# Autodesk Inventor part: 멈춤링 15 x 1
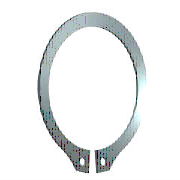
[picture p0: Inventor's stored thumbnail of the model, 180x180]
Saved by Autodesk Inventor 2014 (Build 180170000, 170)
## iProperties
Created: 2012-02
Part Number: 멈춤링 15 x 1
Material: 강철, 연강
Description: 리테이닝 링(C형)
Document SubType Name: Modeling
Standard: KS B 1336
Designer: mduedu
Standards Organization: KS
Language: ko-KR
Size Designation: 15 x 1
Categories: <MemberInstance><Categories><Category DisplayName="샤프트 부품" InternalName="7f7aeb1f-a693-4053-b835-cee3144e0d98" Mnemonic="SHFT"><Category DisplayName="써클립" Inter
Density: 1 g/cm^3
Appearance: 파란색 - 벽 페인트 - 광택
IsCustomPart: 1
Author: mduedu
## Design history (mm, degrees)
sketch "스케치1"
  geometry: L1 (-6, 0)-(6, 0) reference; L2 (0, 20.189)-(0, -80.536) reference; L3 (-48.09, 0)-(48.09, 0) reference; L4 (-0.425, -14.637)-(-0.425, -18.137); L5 (-0.425, -6.54)-(-0.425, -13.29); L6 (-2.795, 2.1)-(3.672, 2.1); L7 (0.425, -6.54)-(0.425, -13.29); L8 (0.425, -14.637)-(0.425, -18.137); C1 r 0.85 at (-1.7, -16.283); C2 r 0.85 at (1.7, -16.283); A1 r 7.15 centre (0, -7.5) between (0.425, -14.637) and (-0.425, -14.637); A2 r 9.075 centre (0, -6.975) between (4.291, -14.971) and (-4.291, -14.971); A3 r 10.646 centre (0, -7.5) between (-2.023, -17.952) and (-0.425, -18.137); A4 r 1.7 centre (-1.7, -16.283) between (-3.397, -16.376) and (-2.023, -17.952); A5 r 1.7 centre (-5.095, -16.469) between (-3.397, -16.376) and (-4.291, -14.971); A6 r 1.7 centre (5.095, -16.469) between (4.291, -14.971) and (3.397, -16.376); A7 r 1.7 centre (1.7, -16.283) between (2.023, -17.952) and (3.397, -16.376); A8 r 10.646 centre (0, -7.5) between (0.425, -18.137) and (2.023, -17.952)
  constraints: 16 point on circle, 12 end point, 10 centre point, 9 symmetric about line, 5 point on line, 4 tangent, 3 coincident, 2 horizontal, 1 perpendicular, 1 vertical, 5 other
  dimensions: "d0" = 14.3 diameter of A1 (= ND); "d1" = 3.5 distance of L4.end L4.start (= SRB2); "d6" = 0.425 distance between parallel lines of L2 L5 (= 0.25 x SD5); "d7" = 2.1 distance between parallel lines of L6 L3 (= SRB1); "d8" = 0.525 distance of A1.centre A2.centre (= 0.25 x SRB1); "d9" = 1.7 radius of A4 (= SD5); "d10" = 1.7 radius of A5 (= SD5); "d11" = 1.275 distance from line of L4 A4.centre (= 0.75 x SD5); "d12" = 1.7 diameter of C1 (= SD5); "d13" = 1.7 diameter of C2 (= SD5); "d14" = 7.5 distance from line of A1.centre L1 (= 0.5 x WD)
extrude "본체" new body sketch "스케치1" distance "d2" = 1 (= SD); taper "d3" = 0 deg
workaxis "Work Axis1"
workplane "Work Plane1"
body "Solid1"
other parameters: "WD" = 15 (= WDMIN) [user parameter; used in 1 equation term], "SD" = 1 [user parameter; used in 1 equation term], "SRB1" = 2.1 [user parameter; used in 2 equation terms], "ND" = 14.3 [user parameter; used in 1 equation term], "SRB2" = 3.5 [user parameter; used in 1 equation term], "SD5" = 1.7 [user parameter; used in 6 equation terms], "d15" = 0, "d16" = 0, "d17" = 0, "d41" = 0, "d42" = 0, "WDMIN" = 15 [user parameter; used in 1 equation term], "SD3" = 13.8 [user parameter], "WDMAX" = 16 [user parameter]
